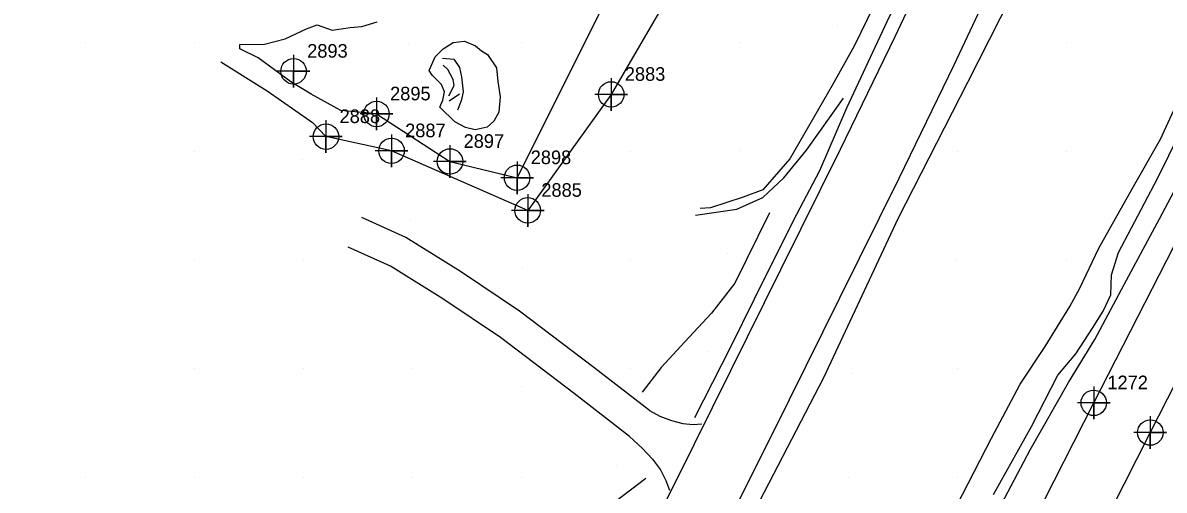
# Model space of a CAD drawing. Extents: x 2062781 to 2066835, y 358981 to 366501.
# Drawn here: x 2064945.6 to 2065155.1, y 363577.2 to 363663.1 of the extents above; entities that cross this region are included whole.
import ezdxf

# ---------------------------------------------------------------- set-up
doc = ezdxf.new("R2010")
doc.units = 0
for name, color, linetype in [('Exist DTM Breakline', 7, 'Continuous'), ('Exist DTM Breakline Cogo Number', 7, 'Continuous'), ('Exist DTM Breakline Cogo Point CELL', 7, 'Continuous'), ('Exist DTM Crownline', 7, 'Continuous'), ('Exist DTM Crownline Cogo Point CELL', 7, 'Continuous'), ('Exist DTM Regular Point CELL', 7, 'Continuous'), ('Exist DTM Regular Point Cogo Number', 7, 'Continuous'), ('Exist DTM Ridgeline', 7, 'Continuous'), ('Exist DTM Ridgeline Cogo Number', 7, 'Continuous'), ('Exist DTM Ridgeline Cogo Point CELL', 7, 'Continuous'), ('Exist Roads EOP', 7, 'Continuous'), ('Exist Roads EOP Cogo Number', 7, 'Continuous'), ('Exist Roads EOP Cogo Point CELL', 7, 'Continuous'), ('PH Exist DTM Breakline', 7, 'Continuous'), ('PH Exist DTM Point', 7, 'Continuous')]:
    doc.layers.add(name, color=color, linetype=linetype)

msp = doc.modelspace()

# ---------------------------------------------------------------- linework, layer by layer
at = {"layer": 'Exist DTM Breakline'}
msp.add_line((2065010.52, 363646.37), (2065003.97, 363646.98), dxfattribs=at)
msp.add_lwpolyline([(2065010.52, 363646.37), (2065024.01, 363637.64), (2065036.33, 363634.65), (2065053.46, 363668.9), (2065074.45, 363696.98), (2065090.09, 363733.97), (2065092.37, 363741.06)], dxfattribs=at)
at = {"layer": 'Exist DTM Breakline Cogo Point CELL'}
for points in [[(2065010.52, 363649.37), (2065010.52, 363643.37), (2065010.52, 363646.37), (2065013.52, 363646.37), (2065007.52, 363646.37)], [(2065010.52, 363649.37), (2065010.52, 363643.37), (2065010.52, 363646.37), (2065013.52, 363646.37), (2065007.52, 363646.37)], [(2065010.52, 363649.37), (2065010.52, 363643.37), (2065010.52, 363646.37), (2065013.52, 363646.37), (2065007.52, 363646.37)], [(2065024.01, 363640.64), (2065024.01, 363634.64), (2065024.01, 363637.64), (2065027.01, 363637.64), (2065021.01, 363637.64)], [(2065024.01, 363640.64), (2065024.01, 363634.64), (2065024.01, 363637.64), (2065027.01, 363637.64), (2065021.01, 363637.64)], [(2065024.01, 363640.64), (2065024.01, 363634.64), (2065024.01, 363637.64), (2065027.01, 363637.64), (2065021.01, 363637.64)], [(2065036.33, 363637.65), (2065036.33, 363631.65), (2065036.33, 363634.65), (2065039.33, 363634.65), (2065033.33, 363634.65)], [(2065036.33, 363637.65), (2065036.33, 363631.65), (2065036.33, 363634.65), (2065039.33, 363634.65), (2065033.33, 363634.65)], [(2065036.33, 363637.65), (2065036.33, 363631.65), (2065036.33, 363634.65), (2065039.33, 363634.65), (2065033.33, 363634.65)]]:
    msp.add_lwpolyline(points, dxfattribs=at)
for centre in [(2065010.52, 363646.37), (2065010.52, 363646.37), (2065010.52, 363646.37), (2065024.01, 363637.64), (2065024.01, 363637.64), (2065024.01, 363637.64), (2065036.33, 363634.65), (2065036.33, 363634.65), (2065036.33, 363634.65)]:
    msp.add_circle(centre, 2.34, dxfattribs=at)
at = {"layer": 'Exist DTM Crownline'}
msp.add_lwpolyline([(2065217.01, 363714.68), (2065196.35, 363673.64), (2065174.3, 363630.59), (2065152.56, 363587.83), (2065130.72, 363544.64), (2065108.77, 363501.62), (2065086.81, 363458.41), (2065065.54, 363417.19), (2065043.91, 363374.76), (2065021.64, 363330.63), (2064998.89, 363286.49), (2064977.54, 363245.06), (2064956.39, 363203.13), (2064934.95, 363161.47)], dxfattribs=at)
at = {"layer": 'Exist DTM Crownline Cogo Point CELL'}
msp.add_lwpolyline([(2065152.56, 363590.83), (2065152.56, 363584.83), (2065152.56, 363587.83), (2065155.56, 363587.83), (2065149.56, 363587.83)], dxfattribs=at)
msp.add_lwpolyline([(2065152.56, 363590.83), (2065152.56, 363584.83), (2065152.56, 363587.83), (2065155.56, 363587.83), (2065149.56, 363587.83)], dxfattribs=at)
msp.add_lwpolyline([(2065152.56, 363590.83), (2065152.56, 363584.83), (2065152.56, 363587.83), (2065155.56, 363587.83), (2065149.56, 363587.83)], dxfattribs=at)
msp.add_circle((2065152.56, 363587.83), 2.34, dxfattribs=at)
msp.add_circle((2065152.56, 363587.83), 2.34, dxfattribs=at)
msp.add_circle((2065152.56, 363587.83), 2.34, dxfattribs=at)
at = {"layer": 'Exist DTM Regular Point CELL'}
msp.add_lwpolyline([(2064995.3, 363657.21), (2064995.3, 363651.21), (2064995.3, 363654.21), (2064998.3, 363654.21), (2064992.3, 363654.21)], dxfattribs=at)
msp.add_circle((2064995.3, 363654.21), 2.34, dxfattribs=at)
at = {"layer": 'Exist DTM Ridgeline'}
msp.add_line((2065001.24, 363642.2), (2064998.76, 363644.78), dxfattribs=at)
msp.add_lwpolyline([(2064951.38, 363896.32), (2064955.31, 363889.4), (2064987.27, 363870.28), (2065023.16, 363849.32), (2065051.23, 363837.17), (2065091.18, 363813.74), (2065101.41, 363806.63), (2065102.38, 363786.44), (2065107.69, 363763.06), (2065094.48, 363729.51), (2065086.75, 363709.39), (2065068.76, 363676.11), (2065053.6, 363649.96), (2065038.28, 363628.65), (2065013.28, 363639.59), (2065001.24, 363642.2)], dxfattribs=at)
at = {"layer": 'Exist DTM Ridgeline Cogo Point CELL'}
for points in [[(2065053.6, 363652.96), (2065053.6, 363646.96), (2065053.6, 363649.96), (2065056.6, 363649.96), (2065050.6, 363649.96)], [(2065053.6, 363652.96), (2065053.6, 363646.96), (2065053.6, 363649.96), (2065056.6, 363649.96), (2065050.6, 363649.96)], [(2065053.6, 363652.96), (2065053.6, 363646.96), (2065053.6, 363649.96), (2065056.6, 363649.96), (2065050.6, 363649.96)], [(2065001.24, 363645.2), (2065001.24, 363639.2), (2065001.24, 363642.2), (2065004.24, 363642.2), (2064998.24, 363642.2)], [(2065001.24, 363645.2), (2065001.24, 363639.2), (2065001.24, 363642.2), (2065004.24, 363642.2), (2064998.24, 363642.2)], [(2065001.24, 363645.2), (2065001.24, 363639.2), (2065001.24, 363642.2), (2065004.24, 363642.2), (2064998.24, 363642.2)], [(2065013.28, 363642.59), (2065013.28, 363636.59), (2065013.28, 363639.59), (2065016.28, 363639.59), (2065010.28, 363639.59)], [(2065013.28, 363642.59), (2065013.28, 363636.59), (2065013.28, 363639.59), (2065016.28, 363639.59), (2065010.28, 363639.59)], [(2065013.28, 363642.59), (2065013.28, 363636.59), (2065013.28, 363639.59), (2065016.28, 363639.59), (2065010.28, 363639.59)], [(2065038.28, 363631.65), (2065038.28, 363625.65), (2065038.28, 363628.65), (2065041.28, 363628.65), (2065035.28, 363628.65)], [(2065038.28, 363631.65), (2065038.28, 363625.65), (2065038.28, 363628.65), (2065041.28, 363628.65), (2065035.28, 363628.65)], [(2065038.28, 363631.65), (2065038.28, 363625.65), (2065038.28, 363628.65), (2065041.28, 363628.65), (2065035.28, 363628.65)]]:
    msp.add_lwpolyline(points, dxfattribs=at)
for centre in [(2065053.6, 363649.96), (2065053.6, 363649.96), (2065053.6, 363649.96), (2065001.24, 363642.2), (2065001.24, 363642.2), (2065001.24, 363642.2), (2065013.28, 363639.59), (2065013.28, 363639.59), (2065013.28, 363639.59), (2065038.28, 363628.65), (2065038.28, 363628.65), (2065038.28, 363628.65)]:
    msp.add_circle(centre, 2.34, dxfattribs=at)
at = {"layer": 'Exist Roads EOP'}
msp.add_lwpolyline([(2064924.53, 363165.86), (2064945.98, 363208.56), (2064967.54, 363250.49), (2064989.15, 363292.73), (2065011.25, 363336.17), (2065033.42, 363380.06), (2065054.8, 363422.19), (2065076.34, 363464.52), (2065098.23, 363506.8), (2065120.26, 363550.17), (2065142.18, 363593.29), (2065163.65, 363635.29), (2065185.52, 363678.33), (2065206.96, 363720.75)], dxfattribs=at)
at = {"layer": 'Exist Roads EOP Cogo Point CELL'}
msp.add_lwpolyline([(2065142.18, 363596.29), (2065142.18, 363590.29), (2065142.18, 363593.29), (2065145.18, 363593.29), (2065139.18, 363593.29)], dxfattribs=at)
msp.add_lwpolyline([(2065142.18, 363596.29), (2065142.18, 363590.29), (2065142.18, 363593.29), (2065145.18, 363593.29), (2065139.18, 363593.29)], dxfattribs=at)
msp.add_lwpolyline([(2065142.18, 363596.29), (2065142.18, 363590.29), (2065142.18, 363593.29), (2065145.18, 363593.29), (2065139.18, 363593.29)], dxfattribs=at)
msp.add_circle((2065142.18, 363593.29), 2.34, dxfattribs=at)
msp.add_circle((2065142.18, 363593.29), 2.34, dxfattribs=at)
msp.add_circle((2065142.18, 363593.29), 2.34, dxfattribs=at)
at = {"layer": 'PH Exist DTM Breakline'}
for points in [[(2065057.06, 363562.14), (2065065.51, 363578.98), (2065075.56, 363599.25), (2065084.83, 363617.92), (2065095.67, 363639.87), (2065105.74, 363660.58), (2065114.57, 363679.45), (2065121.68, 363694.18), (2065129.55, 363710.3), (2065138.15, 363727.84), (2065146.49, 363742.67), (2065159.29, 363767.27), (2065172.03, 363791.33), (2065185.88, 363817.49), (2065195.77, 363835.98), (2065207.33, 363857.58), (2065219.75, 363880.93), (2065229.35, 363899.01), (2065240.29, 363919.45), (2065251.76, 363941.03), (2065258.11, 363954.08)], [(2065076.25, 363573.62), (2065086.31, 363593.91), (2065095.58, 363612.59), (2065106.45, 363634.59), (2065116.57, 363655.42), (2065125.41, 363674.3), (2065132.47, 363688.94), (2065140.33, 363705.03), (2065148.78, 363722.26), (2065157.04, 363736.96), (2065169.92, 363761.69), (2065182.63, 363785.72), (2065196.48, 363811.85), (2065206.35, 363830.32), (2065217.92, 363851.93), (2065230.35, 363875.3), (2065239.93, 363893.36), (2065250.88, 363913.8), (2065262.46, 363935.59), (2065268.9, 363948.84)], [(2065268.62, 363942.79), (2065254.53, 363916.48), (2065242.76, 363892.41), (2065226.1, 363860.35), (2065209.12, 363828.93), (2065190.58, 363793.89), (2065174.31, 363763.52), (2065157.16, 363729.91), (2065145.2, 363704.75), (2065132.93, 363679.7), (2065119.03, 363652.12), (2065106.22, 363627.1), (2065092.6, 363597.9), (2065077.55, 363568.88)], [(2065123.78, 363576.48), (2065130.75, 363588.96), (2065135.56, 363598.36), (2065138.88, 363602.3), (2065141.92, 363607.03), (2065143.92, 363610.15), (2065145.29, 363613.13), (2065145.44, 363616.8), (2065146.72, 363620.94), (2065153.87, 363634.52), (2065162.21, 363651.41), (2065171.18, 363668.27), (2065178.96, 363683.47), (2065188.19, 363700.56), (2065192.27, 363710.88), (2065198.57, 363724.59), (2065205.25, 363737.47), (2065209.62, 363745.26), (2065217.83, 363760.6)], [(2065068.96, 363590.59), (2065075.58, 363603.57), (2065079.93, 363612.43), (2065087.04, 363626.82), (2065091.89, 363635.97), (2065096.86, 363647.51), (2065104.28, 363663.36), (2065110.46, 363675.91), (2065115.51, 363686.73), (2065121.89, 363699.05), (2065129.36, 363714.29), (2065137.02, 363730.27), (2065145.11, 363747.49), (2065149, 363756.1)], [(2065149.85, 363755.52), (2065149.74, 363756.24), (2065149.14, 363756.41), (2065147.96, 363755.91), (2065146.05, 363752.34), (2065140.38, 363741.65), (2065134.31, 363728.89), (2065125.55, 363711.67), (2065114.81, 363691.91), (2065108.07, 363678.37), (2065102.93, 363668.55), (2065098.29, 363658.93), (2065094.18, 363651.57), (2065086.37, 363638.1), (2065081.46, 363632.45), (2065077.8, 363631.07), (2065071.81, 363629.13), (2065069.92, 363629)], [(2065031.84, 363394.67), (2065035.5, 363400.74), (2065041.49, 363410.98), (2065049.32, 363427.45), (2065058.87, 363446.96), (2065068.46, 363464.65), (2065075.84, 363479.71), (2065084.88, 363497.79), (2065094.14, 363515.13), (2065104.34, 363535.22), (2065112.89, 363550.97), (2065122.35, 363569.2), (2065130.51, 363584.66), (2065137.53, 363597.03), (2065142.4, 363604.96), (2065147.78, 363615.02), (2065154.26, 363627.11), (2065162.77, 363643.13), (2065171.3, 363660.12), (2065182.82, 363681.85), (2065192.16, 363700.76), (2065197.93, 363713.12), (2065203.76, 363725.75)], [(2065003.97, 363646.98), (2064998.56, 363650.02), (2064994.82, 363652.29), (2064988.8, 363656.69), (2064985.41, 363658.36), (2064985.44, 363659.14), (2064989.98, 363659.21), (2064993.78, 363660.18), (2064997.69, 363662.02), (2064999.65, 363662.73), (2065002.37, 363661.76), (2065005.71, 363662.26), (2065007.82, 363662.45), (2065010.64, 363663.31)], [(2065030.92, 363657.29), (2065032.54, 363654.83), (2065032.81, 363652.35), (2065033.25, 363649.49), (2065032.96, 363646.71), (2065032.04, 363645.06), (2065030.82, 363643.92), (2065028.61, 363643.43), (2065026.86, 363643.91), (2065024.9, 363644.9), (2065022.14, 363647.6), (2065022.67, 363648.9), (2065023, 363650.41), (2065022.45, 363651.76), (2065020.77, 363653.48), (2065020.21, 363654.35), (2065021.3, 363656.86), (2065022.76, 363658.33), (2065024.58, 363659.51), (2065026.69, 363659.75), (2065028.7, 363658.87), (2065029.82, 363657.98), (2065030.92, 363657.29)], [(2065022.65, 363656.63), (2065024.7, 363656.41), (2065025.74, 363654.88), (2065026.14, 363653.2), (2065026.45, 363650.46), (2065026.05, 363648.79), (2065025.39, 363647.06)], [(2064981.96, 363655.95), (2064990.44, 363650.63), (2064998.34, 363645.08), (2064998.76, 363644.78)], [(2065023.81, 363649.72), (2065024.75, 363651.61), (2065024.57, 363652.73), (2065023.64, 363654.52), (2065022.73, 363655.31)], [(2065115.94, 363572.3), (2065123.38, 363586.83), (2065128.68, 363596.73), (2065133.28, 363603.62), (2065137.81, 363611.01), (2065139.61, 363614.35), (2065143.11, 363621.72), (2065149.23, 363632.6), (2065154.41, 363641.73), (2065159.61, 363653.09)], [(2065023.89, 363648.78), (2065025.73, 363650.08)], [(2065069.09, 363627.76), (2065076.67, 363628.89), (2065081.46, 363631.02), (2065085.29, 363634.61), (2065089.46, 363639.7), (2065096.23, 363649.27)], [(2065060.62, 363591.89), (2065050.44, 363599.76), (2065036.78, 363610.15), (2065025.95, 363617.45), (2065015.92, 363623.68), (2065007.82, 363627.35)], [(2065082.66, 363628.19), (2065076.28, 363615.28), (2065072, 363609.78), (2065067.13, 363604.49), (2065062.78, 363599.79), (2065059.3, 363595.28)], [(2065056.95, 363587.14), (2065046.78, 363595), (2065033.28, 363605.28), (2065022.69, 363612.41), (2065013.08, 363618.38), (2065005.35, 363621.89)], [(2065060.62, 363591.89), (2065062.54, 363590.83), (2065064.69, 363590.05), (2065066.78, 363589.49), (2065068.63, 363589.34), (2065070.25, 363589.45)], [(2065056.95, 363587.14), (2065059.29, 363584.96), (2065061.21, 363582.94), (2065062.64, 363580.96), (2065063.66, 363579.05), (2065064.32, 363577.25)], [(2065059.97, 363579.38), (2065047.39, 363569.87), (2065036.04, 363557.92), (2065031.72, 363547.95), (2065027.61, 363542.45), (2065023.51, 363540.5), (2065016.72, 363540.43), (2065006.7, 363541.94), (2064994.68, 363543.8)]]:
    msp.add_lwpolyline(points, dxfattribs=at)
at = {"layer": 'PH Exist DTM Point'}
for p, q in [((2065095.09, 363662.55), (2065095.09, 363662.55)), ((2064957.18, 363659.54), (2064957.18, 363659.54)), ((2064977.11, 363659.52), (2064977.11, 363659.52)), ((2065016.44, 363659.17), (2065016.44, 363659.17)), ((2065037.11, 363659.52), (2065037.11, 363659.52)), ((2065077.11, 363659.52), (2065077.11, 363659.52)), ((2065137.11, 363659.52), (2065137.11, 363659.52)), ((2065018.7, 363642.67), (2065018.7, 363642.67)), ((2064977.11, 363639.52), (2064977.11, 363639.52)), ((2065037.11, 363639.52), (2065037.11, 363639.52)), ((2065057.11, 363639.52), (2065057.11, 363639.52)), ((2065077.13, 363639.57), (2065077.13, 363639.57)), ((2065117.11, 363639.52), (2065117.11, 363639.52)), ((2065137.11, 363639.52), (2065137.11, 363639.52)), ((2064996.85, 363638.06), (2064996.85, 363638.06)), ((2065016.8, 363626.97), (2065016.8, 363626.97)), ((2065075.01, 363620.73), (2065075.01, 363620.73)), ((2064977.11, 363619.52), (2064977.11, 363619.52)), ((2064997.11, 363619.52), (2064997.11, 363619.52)), ((2065057.11, 363619.52), (2065057.11, 363619.52)), ((2065116.96, 363619.57), (2065116.96, 363619.57)), ((2065137.11, 363619.52), (2065137.11, 363619.52)), ((2065037.4, 363618.18), (2065037.4, 363618.18)), ((2065071.45, 363602.64), (2065071.45, 363602.64)), ((2064977.11, 363599.52), (2064977.11, 363599.52)), ((2064997.11, 363599.52), (2064997.11, 363599.52)), ((2065017.11, 363599.52), (2065017.11, 363599.52)), ((2065057.11, 363599.52), (2065057.11, 363599.52)), ((2065097.92, 363598.74), (2065097.92, 363598.74)), ((2065117.11, 363599.52), (2065117.11, 363599.52)), ((2065037.12, 363596.29), (2065037.12, 363596.29)), ((2065140.08, 363594.55), (2065140.08, 363594.55)), ((2065054.49, 363581.84), (2065054.49, 363581.84)), ((2064957.04, 363579.56), (2064957.04, 363579.56)), ((2064977.11, 363579.52), (2064977.11, 363579.52)), ((2064997.11, 363579.52), (2064997.11, 363579.52)), ((2065017.09, 363579.5), (2065017.09, 363579.5)), ((2065037.11, 363579.52), (2065037.11, 363579.52)), ((2065097.11, 363579.52), (2065097.11, 363579.52)), ((2065117.11, 363579.52), (2065117.11, 363579.52))]:
    msp.add_line(p, q, dxfattribs=at)

# ---------------------------------------------------------------- texts
at = {"layer": 'Exist DTM Breakline Cogo Number'}
for s, p in [('2895', (2065013.02, 363648.87)), ('2895', (2065013.02, 363648.87)), ('2895', (2065013.02, 363648.87)), ('2897', (2065026.51, 363640.14)), ('2897', (2065026.51, 363640.14)), ('2897', (2065026.51, 363640.14)), ('2898', (2065038.83, 363637.15)), ('2898', (2065038.83, 363637.15)), ('2898', (2065038.83, 363637.15))]:
    msp.add_text(s, height=2.5, dxfattribs=at).set_placement(p)
at = {"layer": 'Exist DTM Regular Point Cogo Number'}
msp.add_text('2893', height=2.5, dxfattribs=at).set_placement((2064997.8, 363656.71))
msp.add_text('2893', height=2.5, dxfattribs=at).set_placement((2064997.8, 363656.71))
msp.add_text('2893', height=2.5, dxfattribs=at).set_placement((2064997.8, 363656.71))
at = {"layer": 'Exist DTM Ridgeline Cogo Number'}
for s, p in [('2883', (2065056.1, 363652.46)), ('2883', (2065056.1, 363652.46)), ('2883', (2065056.1, 363652.46)), ('2888', (2065003.74, 363644.7)), ('2888', (2065003.74, 363644.7)), ('2888', (2065003.74, 363644.7)), ('2887', (2065015.78, 363642.09)), ('2887', (2065015.78, 363642.09)), ('2887', (2065015.78, 363642.09)), ('2885', (2065040.78, 363631.15)), ('2885', (2065040.78, 363631.15)), ('2885', (2065040.78, 363631.15))]:
    msp.add_text(s, height=2.5, dxfattribs=at).set_placement(p)
at = {"layer": 'Exist Roads EOP Cogo Number'}
msp.add_text('1272', height=2.5, dxfattribs=at).set_placement((2065144.68, 363595.79))
msp.add_text('1272', height=2.5, dxfattribs=at).set_placement((2065144.68, 363595.79))
msp.add_text('1272', height=2.5, dxfattribs=at).set_placement((2065144.68, 363595.79))

doc.saveas('drawing.dxf')
